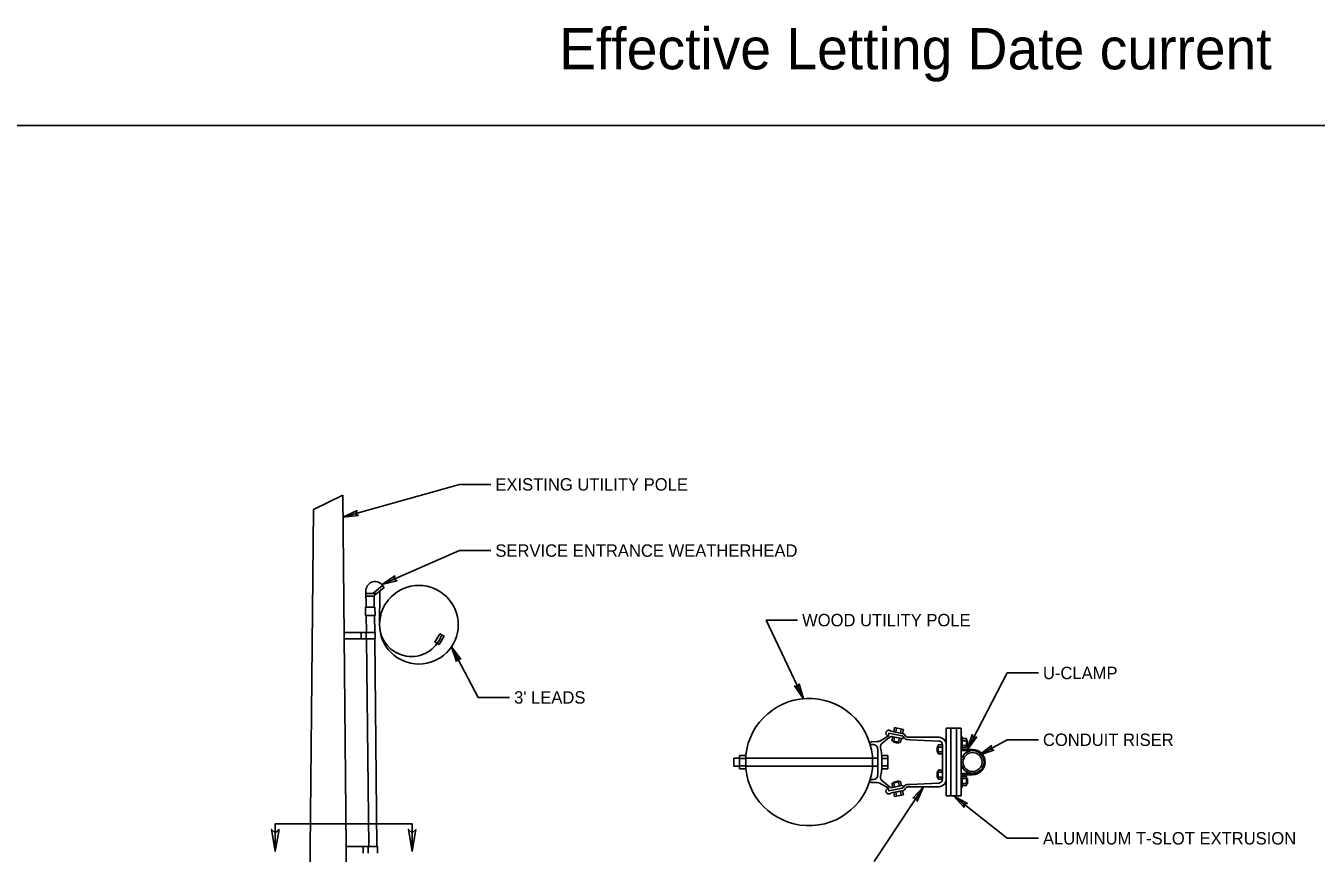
# Model space of a CAD drawing. Extents: x 100006 to 118406, y 96592 to 102182.
# Drawn here: x 106242 to 107492, y 98176 to 98977 of the extents above; entities that cross this region are included whole.
import ezdxf

# ---------------------------------------------------------------- set-up
doc = ezdxf.new("R2010")
doc.units = 0
for name, color, linetype in [('Default', 7, 'Continuous'), ('Level 7', 7, 'Continuous'), ('RD Standard Plans Active', 7, 'Continuous')]:
    doc.layers.add(name, color=color, linetype=linetype)

msp = doc.modelspace()

# ---------------------------------------------------------------- linework, layer by layer
at = {"layer": 'Default'}
msp.add_lwpolyline([(105106.1, 98880.7), (108305.8, 98880.7), (108305.8, 96681.1), (105106.1, 96681.1)], close=True, dxfattribs=at)
at = {"layer": 'Level 7'}
for p, q in [((106549.4, 98501.3), (106662.4, 98533.1)), ((106692.6, 98533.1), (106662.4, 98533.1)), ((106521, 98508.9), (106549.2, 98522.8)), ((106549.2, 98522.8), (106559, 97539.9)), ((106521, 98508.9), (106511.3, 97540.5)), ((106587.1, 98436.1), (106662.4, 98469)), ((106692.6, 98469), (106662.4, 98469)), ((106578.4, 98427.5), (106587.8, 98435.2)), ((106579.7, 98425.5), (106589.3, 98433.3)), ((106587.1, 98436.1), (106589.3, 98433.3)), ((106571.9, 98414.2), (106571.7, 98430)), ((106571.7, 98427.5), (106582.2, 98427.5)), ((106571.8, 98424.9), (106579.7, 98424.9)), ((106579.8, 98414.2), (106579.7, 98425.4)), ((106585.2, 98429.3), (106584.9, 98397.2)), ((106571.3, 98414.2), (106580.4, 98414.2)), ((106571.4, 98406.3), (106571.3, 98414.2)), ((106571.4, 98406.3), (106580.5, 98406.3)), ((106572.3, 98389.7), (106572.1, 98406.4)), ((106580.2, 98389.7), (106580, 98406.3)), ((106580.5, 98406.3), (106580.4, 98414.2)), ((106989.5, 98401.7), (106959.3, 98401.7)), ((106959.3, 98401.7), (106995.4, 98325.6)), ((106580.8, 98389.7), (106550.5, 98389.7)), ((106550.6, 98383.4), (106580.8, 98383.4)), ((106567, 98389.7), (106567, 98383.4)), ((106571.9, 98389.7), (106571.9, 98383.4)), ((106574.5, 98182.3), (106572.4, 98383.4)), ((106582.4, 98182.3), (106580.2, 98383.4)), ((106580.8, 98383.4), (106580.8, 98389.7)), ((106638.5, 98380.4), (106643.4, 98388.5)), ((106638.5, 98380.4), (106642.5, 98378)), ((106642.5, 98378), (106647.5, 98386)), ((106643.4, 98388.5), (106647.5, 98386)), ((106680.5, 98326.8), (106654.5, 98375.9)), ((107192.6, 98350.5), (107154, 98276.4)), ((107222.7, 98350.5), (107192.6, 98350.5)), ((106710.7, 98326.8), (106680.5, 98326.8)), ((107080.1, 98294.2), (107092.2, 98291.7)), ((107082.7, 98293.6), (107083.5, 98297.6)), ((107091.2, 98291.9), (107082.7, 98293.6)), ((107092, 98295.8), (107083.5, 98297.6)), ((107085.4, 98297.2), (107084.6, 98293.2)), ((107090, 98296.2), (107089.2, 98292.3)), ((107092, 98295.8), (107091.2, 98291.9)), ((107147.9, 98296.9), (107133.5, 98296.9)), ((107133.5, 98296.9), (107133.5, 98231.5)), ((107138, 98296.9), (107138, 98231.5)), ((107143.4, 98296.9), (107143.4, 98231.5)), ((107147.9, 98296.9), (107147.9, 98231.5)), ((107066.7, 98283.9), (107061.1, 98284)), ((107061.1, 98281.1), (107063, 98281.1)), ((107077.6, 98289.6), (107069.2, 98284.6)), ((107071.2, 98282.2), (107078.3, 98288.1)), ((107080.9, 98284.8), (107081.7, 98288.7)), ((107089.4, 98283.1), (107080.9, 98284.8)), ((107081.7, 98288.7), (107090.7, 98286.9)), ((107090.2, 98287), (107081.7, 98288.7)), ((107082.4, 98283.5), (107082.6, 98284.5)), ((107084.9, 98283), (107082.4, 98283.5)), ((107083.6, 98288.4), (107082.8, 98284.4)), ((107084.9, 98283), (107087.5, 98282.5)), ((107088.2, 98287.4), (107087.4, 98283.5)), ((107087.5, 98282.5), (107087.7, 98283.4)), ((107090.2, 98287), (107089.4, 98283.1)), ((107095.6, 98286), (107098.3, 98285.8)), ((107126.6, 98288.3), (107096.4, 98288.3)), ((107126.5, 98284.6), (107098.3, 98285.8)), ((107129.8, 98280.8), (107125.8, 98280.8)), ((107125.8, 98280.8), (107125.8, 98272.1)), ((107129.8, 98264.2), (107129.8, 98280.8)), ((107129.8, 98280.8), (107129.8, 98272.1)), ((107133.5, 98264.2), (107133.5, 98280.8)), ((107147.9, 98275.3), (107147.9, 98288.7)), ((107149, 98288.7), (107147.9, 98288.7)), ((107149, 98276.4), (107149, 98288.7)), ((107153, 98286.9), (107149, 98286.9)), ((107149, 98278.2), (107149, 98286.9)), ((107149, 98284.9), (107153, 98284.9)), ((107149, 98280.2), (107153, 98280.2)), ((107153, 98278.2), (107153, 98286.9)), ((107154, 98285.1), (107153, 98285.1)), ((107154, 98282.6), (107154, 98285.1)), ((107154, 98282.6), (107154, 98280)), ((107192.6, 98285.8), (107165.4, 98270.8)), ((107222.7, 98285.8), (107192.6, 98285.8)), ((106928, 98264.2), (106928, 98268.1)), ((106928, 98268.1), (106933.4, 98268.1)), ((106939.5, 98270.7), (106933.4, 98270.7)), ((106933.4, 98270.7), (106933.4, 98257.7)), ((106939.5, 98267.7), (106933.4, 98267.7)), ((106939.5, 98270.7), (106939.5, 98257.7)), ((107062.2, 98268.1), (106939.5, 98268.1)), ((107062.2, 98268.1), (107067.2, 98268.1)), ((107067.2, 98264.2), (107067.2, 98276.8)), ((107071.1, 98270.7), (107077.1, 98270.7)), ((107071.1, 98270.7), (107071.1, 98257.7)), ((107071.1, 98267.7), (107077.1, 98267.7)), ((107077.1, 98270.7), (107077.1, 98257.7)), ((107124.8, 98276.4), (107124.8, 98279)), ((107124.8, 98279), (107125.8, 98279)), ((107124.8, 98276.4), (107124.8, 98273.8)), ((107124.8, 98273.8), (107125.8, 98273.8)), ((107129.8, 98278.8), (107125.8, 98278.8)), ((107129.8, 98274.1), (107125.8, 98274.1)), ((107125.8, 98272.1), (107129.8, 98272.1)), ((107159, 98275.3), (107147.9, 98275.3)), ((107149, 98278.2), (107153, 98278.2)), ((107159, 98276.4), (107149, 98276.4)), ((107154, 98280), (107153, 98280)), ((106928, 98264.2), (106928, 98260.3)), ((106928, 98260.3), (106933.4, 98260.3)), ((106939.5, 98260.7), (106933.4, 98260.7)), ((106933.4, 98257.7), (106939.5, 98257.7)), ((107062.2, 98260.3), (106939.5, 98260.3)), ((107062.2, 98260.3), (107067.2, 98260.3)), ((107067.2, 98264.2), (107067.2, 98251.6)), ((107071.1, 98260.7), (107077.1, 98260.7)), ((107077.1, 98257.7), (107071.1, 98257.7)), ((107125.8, 98256.3), (107129.8, 98256.3)), ((107125.8, 98247.7), (107125.8, 98256.3)), ((107129.8, 98264.2), (107129.8, 98247.7)), ((107129.8, 98247.7), (107129.8, 98256.3)), ((107133.5, 98264.2), (107133.5, 98247.7)), ((107061.1, 98247.3), (107063, 98247.3)), ((107066.7, 98244.5), (107061.1, 98244.5)), ((107077.6, 98238.8), (107069.2, 98243.8)), ((107071.2, 98246.3), (107078.3, 98240.4)), ((107089.4, 98245.3), (107080.9, 98243.6)), ((107080.9, 98243.6), (107081.7, 98239.7)), ((107084.9, 98245.4), (107082.4, 98244.9)), ((107082.4, 98244.9), (107082.6, 98244)), ((107083.6, 98240.1), (107082.8, 98244)), ((107084.9, 98245.4), (107087.5, 98246)), ((107088.2, 98241), (107087.4, 98244.9)), ((107087.5, 98246), (107087.7, 98245)), ((107090.2, 98241.4), (107089.4, 98245.3)), ((107126.5, 98243.8), (107098.3, 98242.6)), ((107124.8, 98252), (107124.8, 98254.6)), ((107124.8, 98254.6), (107125.8, 98254.6)), ((107124.8, 98252), (107124.8, 98249.4)), ((107124.8, 98249.4), (107125.8, 98249.4)), ((107129.8, 98254.3), (107125.8, 98254.3)), ((107129.8, 98249.6), (107125.8, 98249.6)), ((107129.8, 98247.7), (107125.8, 98247.7)), ((107159, 98253.1), (107147.9, 98253.1)), ((107147.9, 98253.1), (107147.9, 98239.7)), ((107159, 98252), (107149, 98252)), ((107149, 98252), (107149, 98239.7)), ((107149, 98250.2), (107153, 98250.2)), ((107149, 98250.2), (107149, 98241.5)), ((107149, 98248.2), (107153, 98248.2)), ((107149, 98243.5), (107153, 98243.5)), ((107153, 98250.2), (107153, 98241.5)), ((107154, 98248.4), (107153, 98248.4)), ((107154, 98243.3), (107153, 98243.3)), ((107154, 98245.9), (107154, 98248.4)), ((107154, 98245.9), (107154, 98243.3)), ((107063.7, 98168), (107111.5, 98240.1)), ((107080.1, 98234.3), (107092.2, 98236.7)), ((107081.7, 98239.7), (107090.7, 98241.5)), ((107090.2, 98241.4), (107081.7, 98239.7)), ((107091.2, 98236.5), (107082.7, 98234.8)), ((107082.7, 98234.8), (107083.5, 98230.8)), ((107092, 98232.6), (107083.5, 98230.8)), ((107085.4, 98231.2), (107084.6, 98235.2)), ((107090, 98232.2), (107089.2, 98236.1)), ((107092, 98232.6), (107091.2, 98236.5)), ((107095.6, 98242.5), (107098.3, 98242.6)), ((107126.6, 98240.1), (107096.4, 98240.1)), ((107147.9, 98231.5), (107133.5, 98231.5)), ((107192.6, 98190.4), (107140.7, 98231.5)), ((107149, 98239.7), (107147.9, 98239.7)), ((107153, 98241.5), (107149, 98241.5)), ((106484, 98204.5), (106616.5, 98204.5)), ((106484, 98204.5), (106484, 98177.9)), ((106616.5, 98204.5), (106616.5, 98177.9)), ((106582.9, 98182.3), (106552.6, 98182.3)), ((106569.2, 98182.3), (106569.2, 98176)), ((106574, 98182.3), (106574, 98176)), ((106582.9, 98176), (106582.9, 98182.3)), ((107222.7, 98190.4), (107192.6, 98190.4))]:
    msp.add_line(p, q, dxfattribs=at)
for points in [[(106564.4, 98502.9), (106549.4, 98501.3), (106563.1, 98507.8), (106561.5, 98504.7)], [(106601.8, 98439.8), (106587.1, 98436.1), (106599.8, 98444.4), (106598.6, 98441.2)], [(106659.3, 98361.5), (106654.5, 98375.9), (106663.7, 98363.9), (106660.4, 98364.8)], [(106991.3, 98340.1), (106995.4, 98325.6), (106986.7, 98338), (106990, 98336.9)], [(107163.1, 98288.5), (107154, 98276.4), (107158.6, 98290.8), (107159.8, 98287.5)], [(107179.7, 98275.8), (107165.4, 98270.8), (107177.3, 98280.2), (107176.4, 98276.9)], [(107101.2, 98229.1), (107111.5, 98240.1), (107105.4, 98226.3), (107104.6, 98229.7)], [(107150.8, 98220.3), (107140.7, 98231.5), (107154, 98224.2), (107150.6, 98223.7)], [(106487.6, 98199), (106484, 98177.9), (106480.4, 98199), (106484, 98195.7)], [(106620.1, 98199), (106616.5, 98177.9), (106612.9, 98199), (106616.5, 98195.7)]]:
    msp.add_lwpolyline(points, close=True, dxfattribs=at)
for points in [[(107077.6, 98289.6), (107078.1, 98292.2), (107090.9, 98289.6)], [(107077.6, 98289.6), (107078.1, 98292.2), (107090.9, 98289.6)], [(107077.6, 98238.8), (107078.1, 98236.2), (107090.9, 98238.8)], [(107077.6, 98238.8), (107078.1, 98236.2), (107090.9, 98238.8)]]:
    msp.add_lwpolyline(points, dxfattribs=at)
for radius in [11.1, 9.24]:
    msp.add_circle((107159, 98264.2), radius, dxfattribs=at)
for centre, radius, start, end in [((106580.6, 98430.2), 8.86, 42.3296, 183.8944), ((107000.7, 98264.2), 61.6, 186.0516, 173.9484), ((107078, 98292.3), 2.79, 154.0949, 261.2651), ((107078, 98292.3), 2.79, 40.6106, 154.0949), ((107061.1, 98282.5), 1.42, 89.7332, 270.2099), ((107062.9, 98276.9), 4.23, 358.4068, 88.4068), ((107066.8, 98288.8), 4.83, 269.7332, 300.7928), ((107075.1, 98278.7), 5.23, 138.2001, 203.7008), ((107080.8, 98284.7), 4.19, 77.0954, 125.9063), ((107090.9, 98288.4), 1.52, 262.209, 345.8356), ((107090.1, 98287.4), 2.43, 16.4092, 68.9593), ((107090.1, 98287.4), 2.43, 16.4092, 68.9593), ((107091.3, 98289.4), 2.43, 16.4092, 68.9593), ((107096, 98290), 4.08, 209.0427, 264.8121), ((107096.7, 98291.8), 3.53, 208.3116, 264.0811), ((107126, 98280.8), 3.86, 360, 82.2414), ((107126, 98280.8), 7.58, 360, 82.2414), ((107001.6, 98264.1), 69.8, 5.4453, 10.305), ((107159, 98264.2), 12.2, 270, 90), ((107159, 98264.2), 11.1, 270, 90), ((107001.6, 98264.3), 69.8, 349.695, 354.5547), ((107061.1, 98245.9), 1.42, 89.7901, 270.2668), ((107062.9, 98251.5), 4.23, 271.5932, 1.5932), ((107066.8, 98239.6), 4.83, 59.2072, 90.2668), ((107075.1, 98249.8), 5.23, 156.2992, 221.7999), ((107126, 98247.7), 3.86, 277.7586, 360), ((107126, 98247.7), 7.58, 277.7586, 360), ((107078, 98236.1), 2.79, 98.7349, 205.9051), ((107078, 98236.1), 2.79, 205.9051, 319.3894), ((107080.8, 98243.8), 4.19, 234.0937, 282.9046), ((107090.9, 98240), 1.52, 14.1644, 97.791), ((107090.1, 98241.1), 2.43, 291.0407, 343.5908), ((107090.1, 98241.1), 2.43, 291.0407, 343.5908), ((107091.3, 98239), 2.43, 291.0407, 343.5908), ((107096, 98238.4), 4.08, 95.1879, 150.9573), ((107096.7, 98236.6), 3.53, 95.9189, 151.6884)]:
    msp.add_arc(centre, radius, start, end, dxfattribs=at)
msp.add_ellipse((106623, 98397.2), major_axis=(38.1, 0), ratio=0.999976, dxfattribs=at)
msp.add_ellipse((106615.8, 98397.2), major_axis=(30.8, 0), ratio=0.999976, start_param=3.141593, end_param=5.939982, dxfattribs=at)

# ---------------------------------------------------------------- texts
for s, p in [(' EXISTING UTILITY POLE', (106692.6, 98527.1)), (' SERVICE ENTRANCE WEATHERHEAD', (106692.6, 98463)), (' WOOD UTILITY POLE', (106989.5, 98395.7)), (' U-CLAMP', (107222.7, 98344.5)), (" 3' LEADS", (106710.7, 98320.8)), (' CONDUIT RISER', (107222.7, 98279.8)), (' ALUMINUM T-SLOT EXTRUSION', (107222.7, 98184.4))]:
    msp.add_text(s, height=12, dxfattribs=at).set_placement(p)
at = {"layer": 'RD Standard Plans Active'}
msp.add_text('Effective Letting Date current', height=40, dxfattribs=at).set_placement((106758.8, 98935))

doc.saveas('drawing.dxf')
